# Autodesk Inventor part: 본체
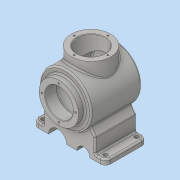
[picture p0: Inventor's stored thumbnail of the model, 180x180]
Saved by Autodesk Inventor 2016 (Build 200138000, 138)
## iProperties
Created: 2018-08
Part Number: 본체
Material: 일반
Document SubType Name: Modeling
Designer: 605-07
Density: 1 g/cm^3
Appearance: 기본값
Author: 605-07
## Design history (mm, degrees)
sketch "스케치1"
  geometry: L1 (70, 40)-(-70, 40); L2 (-70, 40)-(-70, -40); L3 (-70, -40)-(70, -40); L4 (70, -40)-(70, 40); L5 (70, 40)-(-70, -40); L6 (-70, 40)-(70, -40); 1 further point
  constraints: 12 end point, 2 midpoint, 2 parallel, 1 horizontal, 1 perpendicular
  dimensions: "d0" = 140 distance of L1.start L1.end; "d1" = 80 distance of L1.end L2.end
extrude "돌출1" new body sketch "스케치1" distance "d2" = 10; taper "d3" = 0 deg
fillet "모깎기1" dims "d4" = 10
sketch "스케치2"
  geometry: L1 (120, 10)-(0, 10) reference; L2 (10, 10)-(10, 38.563); L3 (-10, 10)-(-10, 0) reference; L4 (110, 10)-(110, 38.563); L5 (130, 0)-(130, 10) reference; L6 (10, 38.563)-(60, 109.97); L7 (110, 38.563)-(60, 109.97); L8 (-10, 0)-(-10, 10) reference; L9 (10, 38.563)-(-10, 10); L10 (110, 38.563)-(130, 10); L11 (10, 10)-(110, 10); 1 further point
  constraints: 14 end point, 3 point on line, 2 collinear, 2 vertical, 1 perpendicular
  dimensions: "d5" = 20 distance between parallel lines of L2 L3; "d6" = 20 distance between parallel lines of L5 L4; "d7" = 35 deg angle of L3 L6; "d8" = 35 deg angle of L5 L7
extrude "돌출2" join sketch "스케치2" distance "d9" = 80; taper "d10" = 0 deg
node "작업 평면1"
sketch "스케치3"
  geometry: C1 r 50 at (60, 82); 1 further point
  constraints: 1 centre point, 1 vertical alignment
  dimensions: "d12" = 82 distance of C1.centre point (60, 0); "d13" = 100 diameter of C1
extrude "돌출3" join sketch "스케치3" distance "d14" = 108; taper "d15" = 0 deg
sketch "스케치4"
  geometry: L1 (32, -60)-(132, -60) reference; L2 (32, 48)-(132, 48) reference; L3 (82, 56)-(82, -60); L4 (82, -60)-(132, -60); L5 (132, -60)-(132, -48.671); A1 r 116 centre (82, 56) between (82, -60) and (132, -48.671); 2 further points
  constraints: 6 end point, 2 midpoint, 2 point on circle, 1 centre point, 1 horizontal, 1 perpendicular, 1 tangent, 1 vertical, 1 vertical alignment
  dimensions: "d16" = 116 radius of A1; "d17" = 50 distance of L3.end L4.end
revolve "회전1" sketch "스케치4" stored, may be unused: angle "d18" = 90 deg
sketch "스케치5"
  geometry: C1 r 50 at (0, 0) reference; C2 r 38 at (0, 0); 1 further point
  constraints: 1 centre point, 1 coincident
  dimensions: "d19" = 76 diameter of C2
extrude "돌출4" join sketch "스케치5" distance "d20" = 12; taper "d21" = 0 deg
sketch "스케치6"
  geometry: L1 (120, 0)-(0, 0) reference; C1 r 17.5 at (37.5, 0); C2 r 12.5 at (87.5, 0); 1 further point
  constraints: 2 centre point, 2 point on line
  dimensions: "d22" = 22.5 distance of point (60, 0) C1.centre; "d23" = 17.5 radius of C1; "d24" = 27.5 distance of C2.centre point (60, 0); "d25" = 12.5 radius of C2
extrude "돌출5" cut sketch "스케치6" stored distance "d26" = 12; taper "d27" = 0 deg
sketch "스케치7"
  geometry: C1 r 38 at (0, 0) reference; C2 r 27 at (0, 0); 1 further point
  constraints: 1 centre point, 1 coincident
  dimensions: "d28" = 54 diameter of C2
extrude "돌출6" cut sketch "스케치7" distance "d29" = 22; taper "d30" = 0 deg
sketch "스케치8"
  geometry: L1 (122, 38)-(82, 38); L2 (82, 38)-(82, -50); L3 (122, -42.163)-(122, 38); L4 (55, 38)-(109, 38) reference; L5 (132, 48)-(132, -48.671) reference; A1 r 116 centre (82, 56) between (32, -48.671) and (132, -48.671) reference; A2 r 106 centre (82, 56) between (82, -50) and (122, -42.163); 1 further point
  constraints: 6 end point, 2 point on circle, 1 centre point, 1 collinear, 1 horizontal, 1 parallel, 1 perpendicular
  dimensions: "d31" = 10 distance between parallel lines of L3 L5; "d32" = 40 distance between parallel lines of L2 L3; "d33" = 10 radial gap between concentric circles of A1 A2
revolve "회전2" sketch "스케치8" stored, may be unused: angle "d34" = 90 deg
node "작업 평면2"
sketch "스케치9"
  geometry: L1 (-50, 48)-(50, 48) reference; C1 r 38 at (0, -2); 1 further point
  constraints: 1 centre point, 1 vertical alignment
  dimensions: "d36" = 50 distance from line of L1 C1.centre; "d37" = 76 diameter of C1
extrude "돌출7" join sketch "스케치9" stored distance "d38" = 22; taper "d39" = 0 deg
sketch "스케치10"
  geometry: C1 r 38 at (0, 0) reference; C2 r 27 at (0, 0); 1 further point
  constraints: 1 centre point, 1 coincident
  dimensions: "d40" = 54 diameter of C2
extrude "돌출8" cut sketch "스케치10" stored distance "d41" = 22; taper "d42" = 0 deg
sketch "스케치11"
  geometry: C1 r 27 at (0, 0) reference; 2 further points
  constraints: 1 vertical alignment
  dimensions: "d43" = 32.5 distance of C1.centre point (0, 32.5)
hole "구멍1" sketch "스케치11" at (0, 32.5) diameter "d44" = 3.242; stored, may be unused: countersink angle "d48" = 90 deg, drill point angle "d50" = 118 deg; dims "d45" = 8, "d46" = 4, "d47" = 2, "d49" = 10
sketch "스케치12"
  geometry: C1 r 27 at (0, 0) reference; 2 further points
  constraints: 1 vertical alignment
  dimensions: "d54" = 32.5 distance of C1.centre point (0, 32.5)
hole "구멍2" sketch "스케치12" at (0, 32.5) diameter "d55" = 3.242; stored, may be unused: countersink angle "d59" = 90 deg, drill point angle "d61" = 118 deg; dims "d56" = 8, "d57" = 4, "d58" = 2, "d60" = 10
fillet "모깎기3" dims "d66" = 3
fillet "모깎기4" dims "d67" = 3
chamfer "모따기1" distance "d68" = 1; stored, may be unused: second distance "d69" = 2, angle "d70" = 45 deg
sketch "스케치15"
  geometry: L1 (-70, 30)-(-67, 30) reference; L2 (70, 30)-(67, 30) reference; L3 (70, -30)-(67, -30) reference; L4 (-60, -40)-(-60, -37) reference; L5 (-70, -30)-(-67, -30) reference; L6 (60, -40)-(60, -37) reference; L7 (60, 40)-(60, 37) reference; L8 (-60, 40)-(-60, 37) reference; A1 r 7 centre (-60, 30) between (-60, 37) and (-67, 30) reference; A2 r 10 centre (-60, 30) between (-60, 40) and (-70, 30) reference; A3 r 7 centre (60, 30) between (67, 30) and (60, 37) reference; A4 r 10 centre (60, 30) between (70, 30) and (60, 40) reference; A5 r 7 centre (60, -30) between (60, -37) and (67, -30) reference; A6 r 10 centre (60, -30) between (60, -40) and (70, -30) reference; A7 r 7 centre (-60, -30) between (-67, -30) and (-60, -37) reference; A8 r 10 centre (-60, -30) between (-70, -30) and (-60, -40) reference; 5 further points
  constraints: 4 coincident
hole "구멍3" sketch "스케치15" at (-60, 30), (-60, -30), (60, -30), (60, 30) diameter "d81" = 8; stored, may be unused: countersink angle "d85" = 90 deg, drill point angle "d87" = 118 deg; dims "d82" = 8, "d83" = 4, "d84" = 2, "d86" = 10
fillet "모깎기5" dims "d88" = 3
fillet "모깎기7" dims "d90" = 3
node "솔리드1"
pattern_circular "원형 패턴1" dims angle "d52" = 360 deg
pattern_circular "원형 패턴2" dims angle "d63" = 360 deg
node "투영된 루프1"
node "투영된 루프2"
node "투영된 루프3"
node "투영된 루프4"
other parameters: "d11" = 8, "d35" = 147
